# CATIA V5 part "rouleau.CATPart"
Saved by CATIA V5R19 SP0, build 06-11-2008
Part number: rouleau
Publications: "rayon_axe_rouleau"
Bounding box of the stored display mesh (mm): x -4.9 to 4.9, y -5 to 5, z -5 to 5
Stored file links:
  G:\EU_thinkMotion\CFAO_2010\MMS_groupe3\MMS_groupe3\A reprendre\ftixier\florent-tixier\florent-tixier\rouleau.CATPart
  C:\Users\Azote\Desktop\CFAO\coupe_tube1.CATProduct
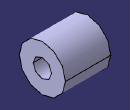
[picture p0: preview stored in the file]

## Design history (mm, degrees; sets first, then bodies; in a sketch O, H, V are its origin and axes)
Parameters
  rayon_axe_rouleau = 2 mm
Set1
  Sketch1 "rouleau", origin (0, -6, 32.3031), H (0, 1, 0), V (0, 0, 1), geometry linked from another document
Body1 (main body)
  Sketch2 on yz-plane, origin (0, 0, 0), H (0, 1, 0), V (0, 0, 1)
    projected circle E1 centre (0, 0) radius 5 from Sketch1
    circle A1 centre (0, 0) radius 2
    radius A1 = 2 {= rayon_axe_rouleau}
    concentricity: A1 E1
  Pad1: profile Sketch2, direction (1, 0, 0), length 4.9, mirrored extent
